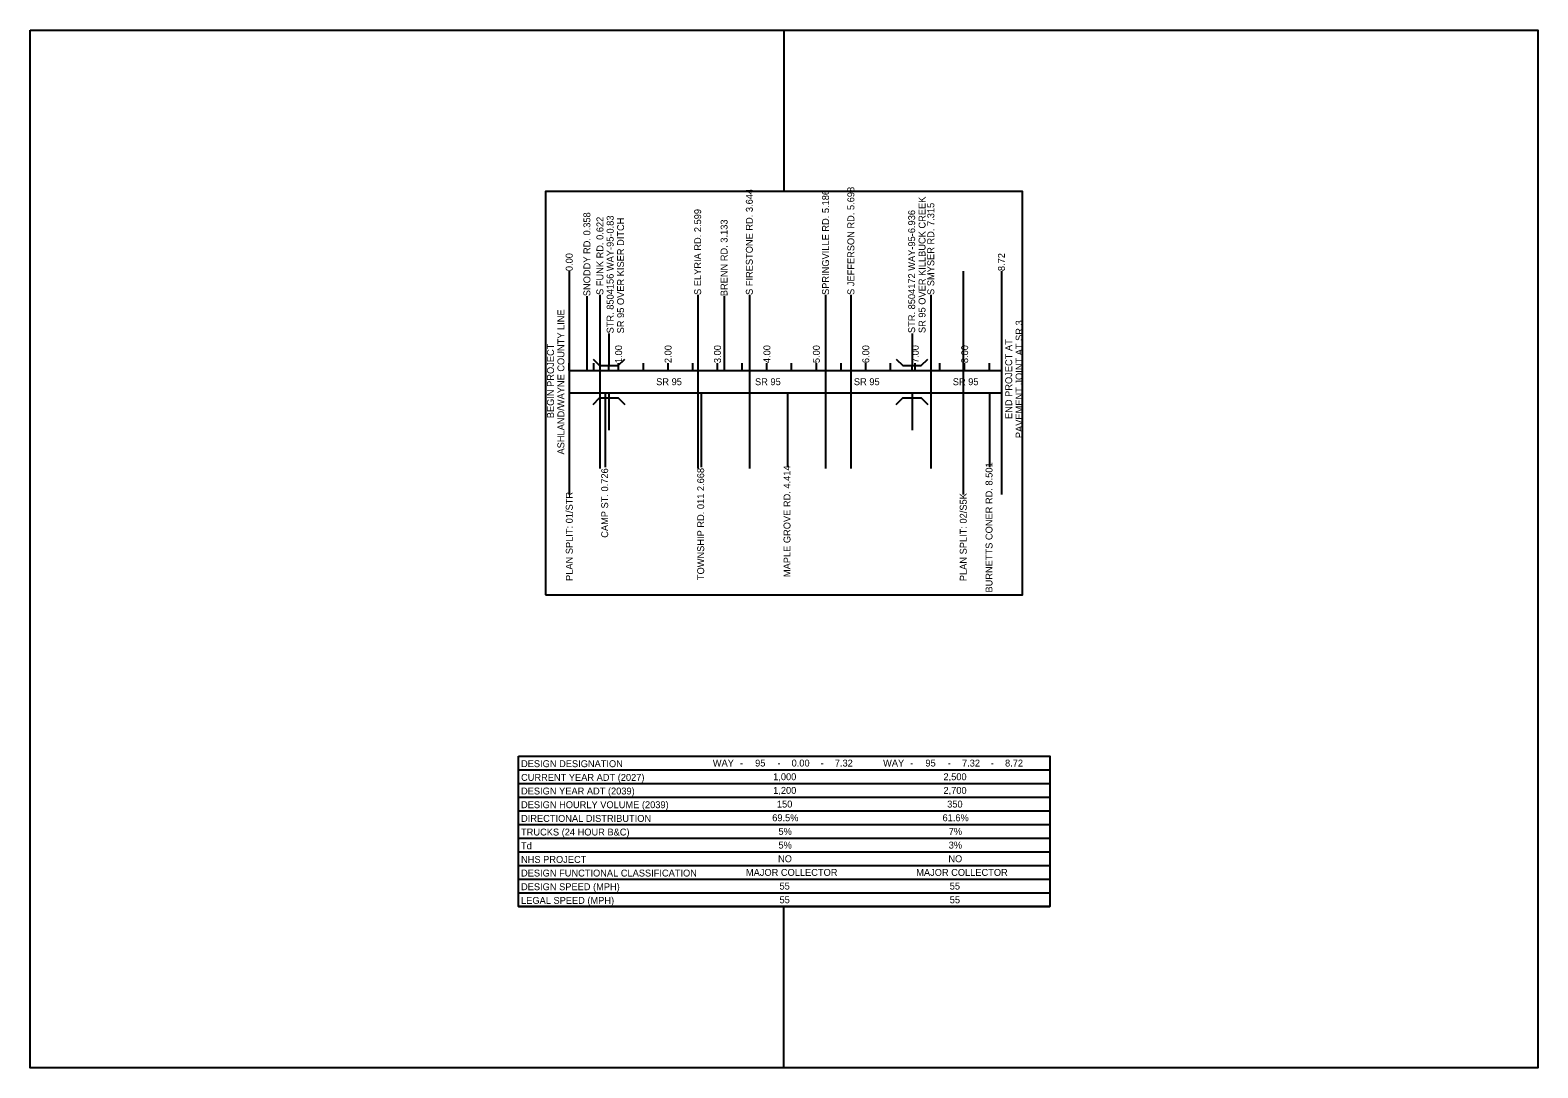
# Model space of a CAD drawing. Extents: x 20550.2 to 20593.9, y 6180.6 to 6241.4.
# Drawn here: x 20551.28 to 20581.78, y 6180.6 to 6201.6 of the extents above; entities that cross this region are included whole.
import ezdxf

# ---------------------------------------------------------------- set-up
doc = ezdxf.new("R2010")
doc.units = 0
for name, color, linetype in [('Default', 7, 'Continuous'), ('DR_X_Culvert', 7, 'Continuous'), ('MD_X_Asphalt_Pavement', 7, 'Continuous'), ('SC_Scratch1', 7, 'Continuous'), ('SH_Data', 7, 'Continuous'), ('SH_Text', 7, 'Continuous')]:
    doc.layers.add(name, color=color, linetype=linetype)

msp = doc.modelspace()

# ---------------------------------------------------------------- linework, layer by layer
at = {"layer": 'Default'}
for p, q in [((20562.186, 6194.71), (20570.93, 6194.71)), ((20562.186, 6194.258), (20570.93, 6194.258))]:
    msp.add_line(p, q, dxfattribs=at)
at = {"layer": 'DR_X_Culvert'}
for p, q in [((20562.989, 6195.462), (20562.989, 6194.81)), ((20569.121, 6195.462), (20569.121, 6194.81)), ((20562.989, 6194.71), (20562.989, 6194.81)), ((20569.121, 6194.71), (20569.121, 6194.81)), ((20562.989, 6194.258), (20562.989, 6194.158)), ((20562.989, 6194.258), (20562.989, 6193.505)), ((20569.121, 6194.258), (20569.121, 6194.158)), ((20569.121, 6194.258), (20569.121, 6193.505))]:
    msp.add_line(p, q, dxfattribs=at)
for points in [[(20562.668, 6194.943), (20562.801, 6194.81), (20563.176, 6194.81), (20563.309, 6194.943)], [(20568.8, 6194.943), (20568.933, 6194.81), (20569.308, 6194.81), (20569.441, 6194.943)], [(20562.668, 6194.025), (20562.801, 6194.158), (20563.176, 6194.158), (20563.309, 6194.025)], [(20568.8, 6194.025), (20568.933, 6194.158), (20569.308, 6194.158), (20569.441, 6194.025)]]:
    msp.add_lwpolyline(points, dxfattribs=at)
at = {"layer": 'MD_X_Asphalt_Pavement'}
for p, q in [((20562.544, 6196.215), (20562.544, 6194.71)), ((20562.808, 6196.24), (20562.808, 6192.728)), ((20564.785, 6196.24), (20564.785, 6192.728)), ((20565.319, 6196.215), (20565.319, 6194.71)), ((20565.83, 6196.24), (20565.83, 6192.728)), ((20567.372, 6196.24), (20567.372, 6192.728)), ((20567.884, 6196.24), (20567.884, 6192.728)), ((20569.501, 6196.24), (20569.501, 6192.728)), ((20562.912, 6194.258), (20562.912, 6192.753)), ((20564.854, 6194.258), (20564.854, 6192.753)), ((20566.6, 6194.258), (20566.6, 6192.753)), ((20570.687, 6194.258), (20570.687, 6192.753))]:
    msp.add_line(p, q, dxfattribs=at)
at = {"layer": 'SC_Scratch1'}
for p, q in [((20566.531, 6201.599), (20566.531, 6198.336)), ((20566.531, 6180.599), (20566.531, 6183.862))]:
    msp.add_line(p, q, dxfattribs=at)
for points in [[(20551.281, 6201.599), (20581.781, 6201.599), (20581.781, 6180.599), (20551.281, 6180.599)], [(20561.706, 6190.168), (20571.356, 6190.168), (20571.356, 6198.336), (20561.706, 6198.336)], [(20561.157, 6186.905), (20571.906, 6186.905), (20571.906, 6183.862), (20561.157, 6183.862)]]:
    msp.add_lwpolyline(points, close=True, dxfattribs=at)
at = {"layer": 'SH_Data'}
for p, q in [((20562.186, 6196.722), (20562.186, 6192.205)), ((20570.156, 6196.722), (20570.156, 6192.205)), ((20570.93, 6196.722), (20570.93, 6192.205)), ((20562.186, 6194.71), (20562.186, 6194.86)), ((20562.686, 6194.71), (20562.686, 6194.86)), ((20563.186, 6194.71), (20563.186, 6194.86)), ((20563.686, 6194.71), (20563.686, 6194.86)), ((20564.186, 6194.71), (20564.186, 6194.86)), ((20564.686, 6194.71), (20564.686, 6194.86)), ((20565.186, 6194.71), (20565.186, 6194.86)), ((20565.686, 6194.71), (20565.686, 6194.86)), ((20566.186, 6194.71), (20566.186, 6194.86)), ((20566.686, 6194.71), (20566.686, 6194.86)), ((20567.186, 6194.71), (20567.186, 6194.86)), ((20567.686, 6194.71), (20567.686, 6194.86)), ((20568.186, 6194.71), (20568.186, 6194.86)), ((20568.686, 6194.71), (20568.686, 6194.86)), ((20569.186, 6194.71), (20569.186, 6194.86)), ((20569.686, 6194.71), (20569.686, 6194.86)), ((20570.186, 6194.71), (20570.186, 6194.86)), ((20570.686, 6194.71), (20570.686, 6194.86)), ((20561.157, 6186.629), (20571.906, 6186.629)), ((20561.157, 6186.352), (20571.906, 6186.352)), ((20561.157, 6186.075), (20571.906, 6186.075)), ((20561.157, 6185.799), (20571.906, 6185.799)), ((20561.157, 6185.522), (20571.906, 6185.522)), ((20561.157, 6185.245), (20571.906, 6185.245)), ((20561.157, 6184.969), (20571.906, 6184.969)), ((20561.157, 6184.692), (20571.906, 6184.692)), ((20561.157, 6184.415), (20571.906, 6184.415)), ((20561.157, 6184.139), (20571.906, 6184.139)), ((20561.157, 6183.862), (20571.906, 6183.862))]:
    msp.add_line(p, q, dxfattribs=at)

# ---------------------------------------------------------------- texts
for s, p in [('DESIGN DESIGNATION', (20561.212, 6186.684)), ('WAY', (20565.091, 6186.697)), ('-', (20565.638, 6186.697)), ('95', (20565.947, 6186.697)), ('-', (20566.399, 6186.697)), ('0.00', (20566.685, 6186.697)), ('-', (20567.271, 6186.697)), ('7.32', (20567.559, 6186.697)), ('WAY', (20568.536, 6186.697)), ('-', (20569.083, 6186.697)), ('95', (20569.392, 6186.697)), ('-', (20569.844, 6186.697)), ('7.32', (20570.132, 6186.697)), ('-', (20570.715, 6186.697)), ('8.72', (20571.003, 6186.697)), ('CURRENT YEAR ADT (2027)', (20561.212, 6186.407)), ('1,000', (20566.312, 6186.42)), ('2,500', (20569.757, 6186.42)), ('DESIGN YEAR ADT (2039)', (20561.212, 6186.131)), ('1,200', (20566.312, 6186.144)), ('2,700', (20569.757, 6186.144)), ('DESIGN HOURLY VOLUME (2039)', (20561.212, 6185.854)), ('DIRECTIONAL DISTRIBUTION', (20561.212, 6185.577)), ('69.5%', (20566.293, 6185.59)), ('150', (20566.388, 6185.867)), ('61.6%', (20569.738, 6185.59)), ('350', (20569.832, 6185.867)), ('TRUCKS (24 HOUR B&C)', (20561.212, 6185.301)), ('5%', (20566.419, 6185.314)), ('7%', (20569.863, 6185.314)), ('Td', (20561.212, 6185.024)), ('5%', (20566.419, 6185.037)), ('3%', (20569.863, 6185.037)), ('NHS PROJECT', (20561.212, 6184.747)), ('NO', (20566.411, 6184.76)), ('NO', (20569.856, 6184.76)), ('DESIGN FUNCTIONAL CLASSIFICATION', (20561.212, 6184.471)), ('MAJOR COLLECTOR', (20565.761, 6184.484)), ('MAJOR COLLECTOR', (20569.206, 6184.484)), ('DESIGN SPEED (MPH)', (20561.212, 6184.194)), ('55', (20566.44, 6184.207)), ('55', (20569.884, 6184.207)), ('LEGAL SPEED (MPH)', (20561.212, 6183.917)), ('55', (20566.44, 6183.93)), ('55', (20569.884, 6183.93))]:
    msp.add_text(s, height=0.14, dxfattribs=at).set_placement(p)
at = {"layer": 'SH_Text'}
for s, height, p in [('S FIRESTONE RD. 3.644', 0.14015, (20565.9, 6196.24)), ('SPRINGVILLE RD. 5.186', 0.14015, (20567.442, 6196.24)), ('S JEFFERSON RD. 5.698', 0.14015, (20567.954, 6196.24)), ('SR 95 OVER KILLBUCK CREEK', 0.14015, (20569.394, 6195.469)), ('S ELYRIA RD. 2.599', 0.14015, (20564.855, 6196.24)), ('STR. 8504172 WAY-95-6.936', 0.14015, (20569.184, 6195.469)), ('S SMYSER RD. 7.315', 0.14015, (20569.571, 6196.24)), ('SNODDY RD. 0.358', 0.14015, (20562.614, 6196.215)), ('S FUNK RD. 0.622', 0.14015, (20562.878, 6196.24)), ('STR. 8504156 WAY-95-0.83', 0.14015, (20563.085, 6195.462)), ('SR 95 OVER KISER DITCH', 0.14015, (20563.296, 6195.462)), ('BRENN RD. 3.133', 0.14015, (20565.389, 6196.215)), ('0.00', 0.1402, (20562.256, 6196.722)), ('8.72', 0.1402, (20571, 6196.722)), ('ASHLAND/WAYNE COUNTY LINE', 0.14015, (20562.088, 6193.011)), ('PAVEMENT JOINT AT SR 3', 0.14015, (20571.357, 6193.342)), ('BEGIN PROJECT', 0.14015, (20561.878, 6193.745)), ('1.00', 0.1402, (20563.256, 6194.86)), ('2.00', 0.1402, (20564.256, 6194.86)), ('3.00', 0.1402, (20565.256, 6194.86)), ('4.00', 0.1402, (20566.256, 6194.86)), ('5.00', 0.1402, (20567.256, 6194.86)), ('6.00', 0.1402, (20568.256, 6194.86)), ('7.00', 0.1402, (20569.256, 6194.86)), ('8.00', 0.1402, (20570.256, 6194.86)), ('END PROJECT AT ', 0.14015, (20571.147, 6193.73)), ('CAMP ST. 0.726', 0.14015, (20562.974, 6191.326)), ('TOWNSHIP RD. 011 2.668', 0.14015, (20564.916, 6190.469)), ('MAPLE GROVE RD. 4.414', 0.14015, (20566.662, 6190.53)), ('BURNETTS CONER RD. 8.501', 0.14015, (20570.749, 6190.217)), ('PLAN SPLIT: 01/STR', 0.14015, (20562.258, 6190.452)), ('PLAN SPLIT: 02/S5K', 0.14015, (20570.228, 6190.448))]:
    msp.add_text(s, height=height, rotation=90, dxfattribs=at).set_placement(p)
for p in [(20563.945, 6194.414), (20565.945, 6194.414), (20567.945, 6194.414), (20569.945, 6194.414)]:
    msp.add_text('SR 95', height=0.1402, dxfattribs=at).set_placement(p)

doc.saveas('drawing.dxf')
